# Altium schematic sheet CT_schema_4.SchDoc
size 283 x 147 mm
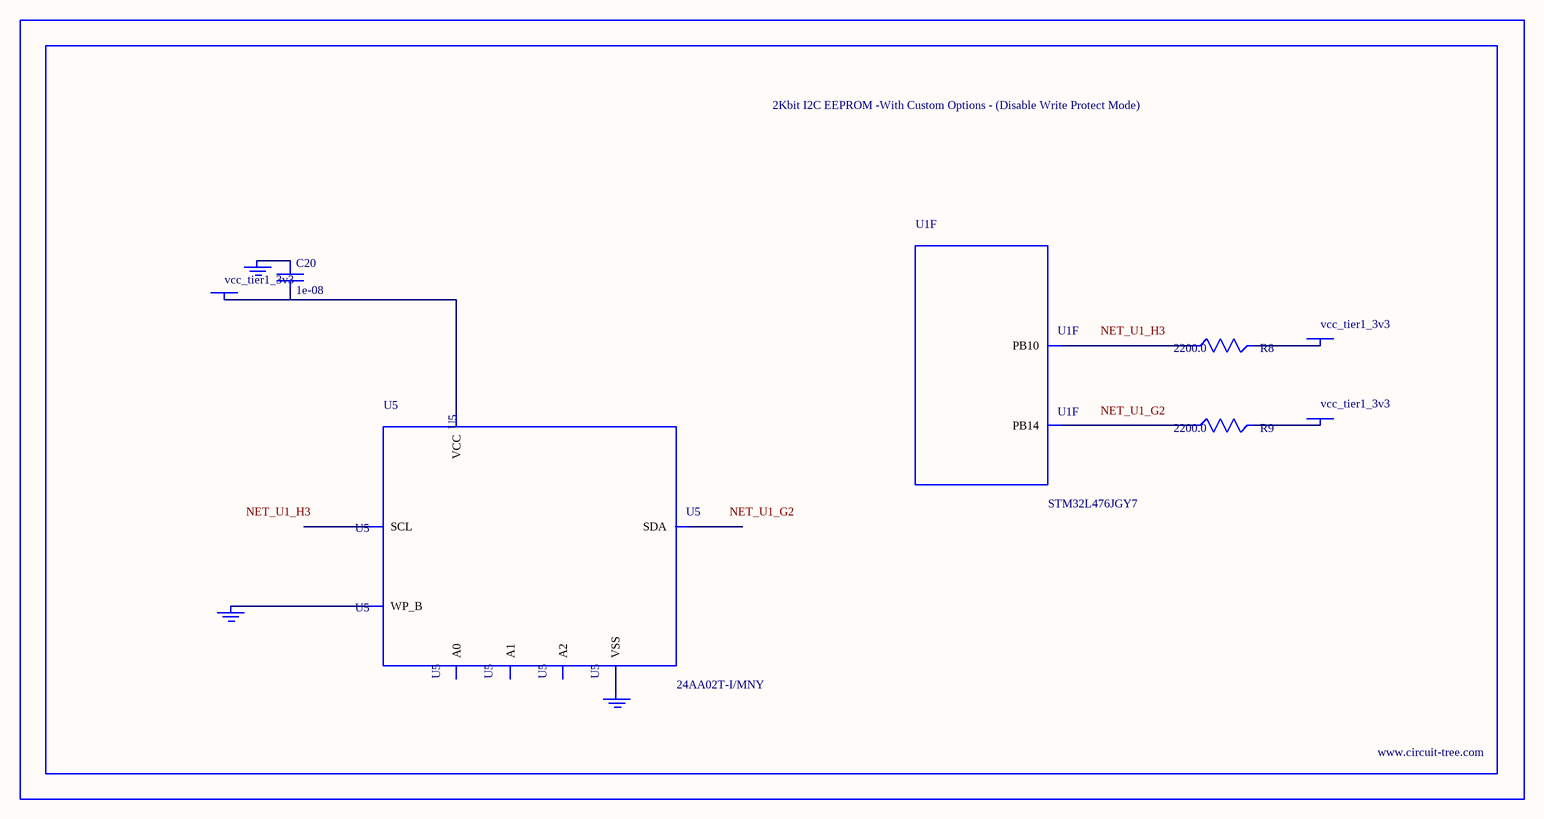
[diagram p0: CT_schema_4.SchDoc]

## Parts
BORDER3  (no value)
C20  1e-08  [C0402]
GND_INSTANCE_3_0  (no value)
GND_INSTANCE_3_1  (no value)
GND_INSTANCE_3_2  (no value)
POWER_INSTANCE_3_0  vcc_tier1_3v3
POWER_INSTANCE_3_1  vcc_tier1_3v3
POWER_INSTANCE_3_2  vcc_tier1_3v3
R8  2200.0  [R0603]
R9  2200.0  [R0603]
U1  STM32L476JGY7  [WLCSP72]  (part F of 8)
U5  24AA02T-I/MNY  [TDFN-8/6MM]

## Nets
NetC20_1: C20.1 GND_INSTANCE_3_1.0(GND)
NetC20_2: C20.2 POWER_INSTANCE_3_0.0(PWR) U5.8(VCC)
NetGND_INSTANCE_3_0_0: GND_INSTANCE_3_0.0(GND) U5.7(WP_B)
NetGND_INSTANCE_3_2_0: GND_INSTANCE_3_2.0(GND) U5.4(VSS)
NetPOWER_INSTANCE_3_1_0: POWER_INSTANCE_3_1.0(PWR) R8.2
NetPOWER_INSTANCE_3_2_0: POWER_INSTANCE_3_2.0(PWR) R9.2
NetR8_1: R8.1 U1.H3(PB10)
NetR9_1: R9.1 U1.G2(PB14)

Not connected (* = marked no-connect by the designer): U5 1(A0) 2(A1) 3(A2) 5(SDA) 6(SCL)

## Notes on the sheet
- Labels drawn without touching a wire or pin: NET_U1_G2, NET_U1_H3

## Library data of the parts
BORDER3 = BORDER_PAGE3
C20 = C0402C103K3RAC
GND_INSTANCE_3_0-GND_INSTANCE_3_2 = GND
POWER_INSTANCE_3_0-POWER_INSTANCE_3_2 = PWR
R8 R9 = RC0603JR-072K2L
